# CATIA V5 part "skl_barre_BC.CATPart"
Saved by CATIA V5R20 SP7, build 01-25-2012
Part number: skl_barre_BC
Publications: "Droite.9", "Droite.10", "Point.B", "Point.C", "Point.I", "Point.J"
Bounding box of the stored display mesh (mm): x -37.5 to 75, y 110 to 190, z -70 to -50
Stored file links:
  D:\IFMA\COURS\2A\projet balance IAO\catia\skl_barre_BC.CATPart
  D:\IFMA\COURS\2A\projet balance IAO\catia\Skl_projet_balance.CATProduct
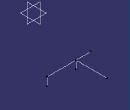
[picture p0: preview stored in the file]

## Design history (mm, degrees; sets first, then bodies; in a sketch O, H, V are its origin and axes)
Set1
  Point1 "Point.B": linked copy from another document
  Point2 "Point.C": linked copy from another document
  Point3 "Point.I": linked copy from another document
  Point4 "Point.J": linked copy from another document
  Plane1 "Plan_BC": linked copy from another document
Body1 (main body)
  Line1: type PtPt, FirstPoint Point1, SecondPoint Point2
  Line2: type PtPt, FirstPoint Point2, SecondPoint Point4
  Line3: type PtDir, RefPoint Point1, Direction xy-plane, Start 0, End 20
  Line4: type PtDir, RefPoint Point2, Direction xy-plane, Start 0, End 20
  Line5: type PtPt, FirstPoint Point2, SecondPoint Point3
